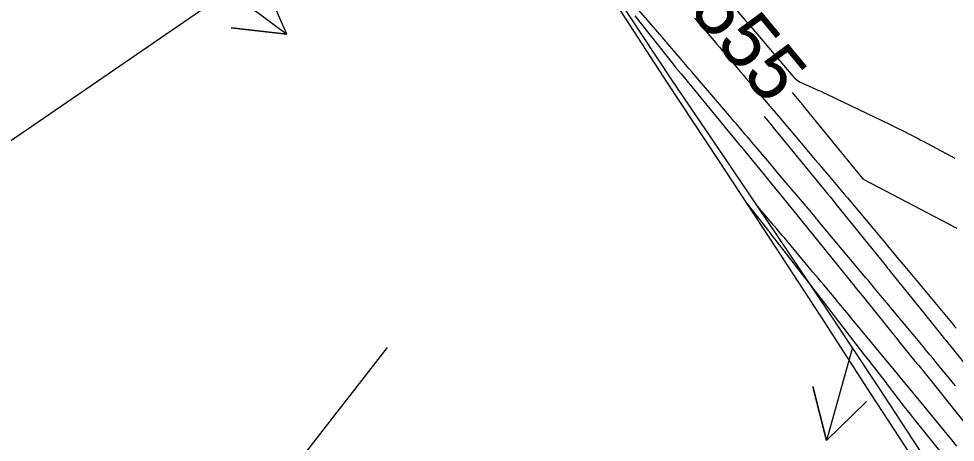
# Model space of a CAD drawing. Extents: x 954385 to 988206, y 1868364 to 1924553.
# Drawn here: x 957517.5 to 957618.2, y 1920108.8 to 1920154.3 of the extents above; entities that cross this region are included whole.
import ezdxf

# ---------------------------------------------------------------- set-up
doc = ezdxf.new("R2010")
doc.units = 0
for name, color, linetype in [('1', 7, 'Continuous'), ('Ex_Major Contours', 7, 'Continuous'), ('Ex_Minor Contours', 7, 'Continuous'), ('Perimeter', 7, 'Continuous'), ('Slopes', 7, 'Continuous')]:
    doc.layers.add(name, color=color, linetype=linetype)

msp = doc.modelspace()

# ---------------------------------------------------------------- linework, layer by layer
at = {"layer": '1'}
for points in [[(957620.08, 1920097.17), (957614.6, 1920105.54), (957609.15, 1920113.92), (957607.25, 1920116.85), (957603.71, 1920122.32), (957598.24, 1920130.69), (957592.75, 1920139.05), (957587.26, 1920147.4), (957581.81, 1920155.79), (957576.32, 1920164.15), (957570.81, 1920172.5), (957567.7, 1920177.52), (957565.55, 1920181.01), (957560.29, 1920189.53), (957544.48, 1920190.91), (957539.51, 1920199.62), (957534.53, 1920208.32), (957529.51, 1920217), (957531.24, 1920230.24), (957525.3, 1920238.3), (957519.39, 1920246.37)], [(957583.73, 1920154.59), (957587.85, 1920149.39), (957587.93, 1920149.29), (957588, 1920149.2), (957588.08, 1920149.1), (957588.16, 1920149.01), (957588.67, 1920148.39), (957588.7, 1920148.36), (957588.7, 1920148.35), (957594.93, 1920140.81), (957595, 1920140.72), (957595.08, 1920140.62), (957595.16, 1920140.53), (957595.23, 1920140.43), (957601.15, 1920133.2), (957601.29, 1920133.02), (957601.43, 1920132.85), (957601.57, 1920132.67), (957601.72, 1920132.5), (957607.34, 1920125.55), (957607.54, 1920125.3), (957607.75, 1920125.04), (957607.95, 1920124.79), (957608.15, 1920124.54), (957611.51, 1920120.36), (957611.67, 1920120.15), (957611.84, 1920119.95), (957612, 1920119.75), (957612.16, 1920119.55), (957613.84, 1920117.47), (957613.94, 1920117.35), (957614.04, 1920117.23), (957614.14, 1920117.11), (957614.24, 1920116.99), (957619.68, 1920110.22)], [(957618.36, 1920131.72), (957618.16, 1920131.83), (957617.95, 1920131.95), (957617.74, 1920132.06), (957617.54, 1920132.17), (957608.4, 1920136.96), (957608.36, 1920136.99), (957608.33, 1920137.02), (957608.29, 1920137.05), (957608.26, 1920137.08), (957608.06, 1920137.33), (957608.05, 1920137.34), (957601.84, 1920144.94), (957601.78, 1920145.02), (957601.71, 1920145.11), (957601.64, 1920145.19), (957601.57, 1920145.27), (957600.69, 1920146.34)], [(957597.62, 1920143.8), (957597.67, 1920143.74), (957598.03, 1920143.3), (957598.39, 1920142.86), (957598.75, 1920142.42), (957599.11, 1920141.98), (957604.16, 1920135.81), (957604.45, 1920135.45), (957604.75, 1920135.09), (957605.04, 1920134.73), (957605.33, 1920134.36), (957610.75, 1920127.67), (957610.9, 1920127.48), (957611.06, 1920127.29), (957611.21, 1920127.09), (957611.37, 1920126.9), (957615.01, 1920122.37), (957615.08, 1920122.28), (957615.15, 1920122.19), (957615.22, 1920122.11), (957615.29, 1920122.02), (957617.01, 1920119.89), (957617.18, 1920119.68), (957617.35, 1920119.47), (957617.52, 1920119.26), (957617.69, 1920119.05), (957623.42, 1920111.93)], [(957595.8, 1920134.4), (957598.09, 1920131.47), (957598.32, 1920131.18), (957598.54, 1920130.89), (957598.77, 1920130.6), (957598.99, 1920130.31), (957603.97, 1920123.88), (957604.32, 1920123.42), (957604.68, 1920122.97), (957605.03, 1920122.51), (957605.38, 1920122.06), (957608.36, 1920118.18), (957608.51, 1920117.99), (957608.66, 1920117.8), (957608.8, 1920117.61), (957608.95, 1920117.42), (957610.73, 1920115.13), (957610.76, 1920115.08), (957610.8, 1920115.04), (957610.83, 1920114.99), (957610.87, 1920114.95), (957612.69, 1920112.58), (957613.01, 1920112.17), (957613.33, 1920111.76), (957613.65, 1920111.36), (957613.97, 1920110.95), (957616.95, 1920107.26)]]:
    msp.add_lwpolyline(points, dxfattribs=at)
at = {"layer": 'Ex_Major Contours'}
msp.add_lwpolyline([(957592.58, 1920157.63), (957595.55, 1920154.16), (957595.62, 1920154.09), (957595.68, 1920154.01), (957595.74, 1920153.94), (957595.8, 1920153.87), (957596.05, 1920153.58), (957596.11, 1920153.51), (957596.17, 1920153.44), (957596.24, 1920153.36), (957596.3, 1920153.29), (957600.71, 1920148.12), (957600.95, 1920147.87), (957601.21, 1920147.65), (957601.5, 1920147.46), (957601.81, 1920147.31), (957603.1, 1920146.76), (957603.42, 1920146.62), (957603.74, 1920146.48), (957604.06, 1920146.33), (957604.37, 1920146.18), (957611.16, 1920142.92), (957611.46, 1920142.78), (957611.76, 1920142.63), (957612.05, 1920142.48), (957612.35, 1920142.33), (957613.53, 1920141.73), (957613.83, 1920141.58), (957614.12, 1920141.43), (957614.41, 1920141.27), (957614.71, 1920141.12), (957618.14, 1920139.28)], dxfattribs=at)
at = {"layer": 'Ex_Minor Contours'}
for points in [[(957618.2, 1920114.81), (957617.51, 1920115.65), (957616.12, 1920117.33), (957615.78, 1920117.75), (957615.43, 1920118.17), (957615.09, 1920118.59), (957614.74, 1920119.01), (957611.25, 1920123.22), (957611.02, 1920123.49), (957610.8, 1920123.76), (957610.58, 1920124.03), (957610.36, 1920124.29), (957609.47, 1920125.37), (957609.24, 1920125.64), (957609.02, 1920125.91), (957608.8, 1920126.17), (957608.57, 1920126.44), (957603.45, 1920132.57), (957603.36, 1920132.67), (957603.27, 1920132.78), (957603.19, 1920132.88), (957603.1, 1920132.99), (957602.75, 1920133.41), (957602.66, 1920133.51), (957602.57, 1920133.62), (957602.48, 1920133.72), (957602.4, 1920133.83), (957599.36, 1920137.41), (957599.04, 1920137.8), (957598.71, 1920138.19), (957598.38, 1920138.58), (957598.05, 1920138.97), (957596.55, 1920140.74), (957596.31, 1920141.02), (957596.08, 1920141.3), (957595.84, 1920141.58), (957595.6, 1920141.85), (957594.66, 1920142.97), (957594.42, 1920143.24), (957594.18, 1920143.52), (957593.95, 1920143.8), (957593.71, 1920144.08), (957590.27, 1920148.1), (957589.91, 1920148.53), (957589.55, 1920148.95), (957589.18, 1920149.38), (957588.82, 1920149.8), (957586.85, 1920152.1), (957586.74, 1920152.22), (957586.64, 1920152.35), (957586.53, 1920152.47), (957586.42, 1920152.59), (957586, 1920153.08), (957585.9, 1920153.21), (957585.79, 1920153.33), (957585.69, 1920153.45), (957585.58, 1920153.58), (957583, 1920156.59)], [(957590.16, 1920154.34), (957590.28, 1920154.2), (957592.23, 1920151.93), (957592.55, 1920151.56), (957592.86, 1920151.19), (957593.17, 1920150.83), (957593.49, 1920150.46), (957594.74, 1920148.99), (957595.06, 1920148.62), (957595.37, 1920148.25), (957595.68, 1920147.88), (957596, 1920147.52), (957598.46, 1920144.63), (957598.93, 1920144.08), (957599.39, 1920143.54), (957599.85, 1920142.99), (957600.32, 1920142.44), (957602.39, 1920139.99), (957602.74, 1920139.57), (957603.09, 1920139.16), (957603.44, 1920138.75), (957603.79, 1920138.33), (957605.19, 1920136.68), (957605.53, 1920136.27), (957605.88, 1920135.86), (957606.23, 1920135.44), (957606.58, 1920135.03), (957610.24, 1920130.65), (957610.45, 1920130.4), (957610.66, 1920130.15), (957610.87, 1920129.9), (957611.08, 1920129.65), (957611.91, 1920128.65), (957612.12, 1920128.4), (957612.33, 1920128.15), (957612.54, 1920127.9), (957612.75, 1920127.65), (957617.93, 1920121.4), (957618.09, 1920121.2), (957618.26, 1920121.01)], [(957618.35, 1920108.34), (957617.8, 1920109.01), (957613.33, 1920114.45), (957612.73, 1920115.19), (957612.12, 1920115.93), (957611.51, 1920116.67), (957610.9, 1920117.4), (957607.63, 1920121.35), (957607.43, 1920121.58), (957607.24, 1920121.81), (957607.05, 1920122.04), (957606.86, 1920122.28), (957606.09, 1920123.2), (957605.9, 1920123.43), (957605.71, 1920123.66), (957605.51, 1920123.9), (957605.32, 1920124.13), (957604.01, 1920125.7), (957603.72, 1920126.04), (957603.44, 1920126.38), (957603.16, 1920126.71), (957602.87, 1920127.05), (957599.84, 1920130.68), (957599.55, 1920131.03), (957599.26, 1920131.37), (957598.96, 1920131.72), (957598.67, 1920132.07), (957596.92, 1920134.15)]]:
    msp.add_lwpolyline(points, dxfattribs=at)
at = {"layer": 'Perimeter'}
msp.add_lwpolyline([(957621.03, 1920097.81), (957615.52, 1920106.16), (957610.04, 1920114.52), (957604.51, 1920122.86), (957598.94, 1920131.16), (957593.33, 1920139.44), (957587.72, 1920147.72), (957584.55, 1920152.49), (957582.19, 1920156.05), (957576.65, 1920164.37), (957571.06, 1920172.67), (957565.83, 1920181.2), (957550.79, 1920183.1), (957545.87, 1920191.85), (957540.97, 1920200.61), (957535.89, 1920209.24), (957530.67, 1920217.78), (957527.96, 1920219.85), (957523.6, 1920225.08), (957518.05, 1920233.39), (957517.7, 1920245.23)], dxfattribs=at)
at = {"layer": 'Slopes'}
for points in [[(957457.13, 1920218.93), (957546.34, 1920152.63), (957540.38, 1920153.32), (957546.34, 1920152.63), (957543.96, 1920158.14)], [(957557.13, 1920168.93), (957420.08, 1920074.89), (957422.67, 1920080.3), (957420.08, 1920074.89), (957426.06, 1920075.36)], [(957557.13, 1920118.93), (957540.28, 1920097.31), (957541.11, 1920103.25), (957540.28, 1920097.31), (957545.84, 1920099.56)], [(957607.13, 1920118.93), (957604.35, 1920108.93), (957602.85, 1920114.74), (957604.35, 1920108.93), (957608.63, 1920113.13)]]:
    msp.add_lwpolyline(points, dxfattribs=at)

# ---------------------------------------------------------------- texts
at = {"layer": '1'}
msp.add_text('555', height=6, rotation=309.633, dxfattribs=at).set_placement((957589.49, 1920155.15))

doc.saveas('drawing.dxf')
